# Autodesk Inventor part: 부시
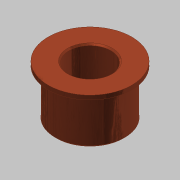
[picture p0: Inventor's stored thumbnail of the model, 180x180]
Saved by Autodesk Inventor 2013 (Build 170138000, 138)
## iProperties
Created: 2015-10
Part Number: 부시
Document SubType Name: Modeling
Designer: mdu
Density: 7.86 g/cm^3
Material: 강철, 연강
Mass: 246.97 g
Surface Area: 129.264 cm^2
Volume: 31.4212 cm^3
Author: mdu
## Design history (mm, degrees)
sketch "스케치1"
  geometry: C1 r 31 at (0, 0) reference; C2 r 25 at (0, 0) reference; C3 r 30 at (0, 0) reference; 1 further point
  node "참조1"
  node "참조2"
  node "참조4"
extrude "돌출1" new body sketch "스케치1" distance "d0" = 3; taper "d1" = 0 deg
extrude "돌출2" join sketch "스케치1" distance "d2" = 36; taper "d3" = 0 deg
chamfer "모따기1" distance "d6" = 1; stored, may be unused: second distance "d7" = 2, angle "d8" = 45 deg
sketch "스케치3"
  geometry: C1 r 15 at (0, 0); 1 further point
  constraints: 1 centre point, 1 coincident
  dimensions: "d13" = 30 diameter of C1
extrude "돌출4" cut sketch "스케치3" stored distance "d14" = 10; taper "d15" = 0 deg
chamfer "모따기3" distance "d16" = 1; stored, may be unused: second distance "d17" = 2, angle "d18" = 45 deg
node "솔리드1"
